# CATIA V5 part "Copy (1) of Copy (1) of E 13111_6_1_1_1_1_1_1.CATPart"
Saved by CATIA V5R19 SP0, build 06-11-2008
Part number: Copy (1) of Copy (1) of E 13111_6_1_1_1_1_1_1
Definition: E 13111_6
Nomenclature: E 13111_6
Source: Unknown
Description: PART-E 13111_6-DESC
Bounding box of the stored display mesh (mm): x -3 to 3, y -3 to 3, z -26 to -8
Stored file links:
  C:\Users\jsmid\Desktop\DP_Smidak_Forma LEGO\Copy (1) of Copy (1) of E 13111_6_1_1_1_1_1_1.CATPart
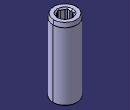
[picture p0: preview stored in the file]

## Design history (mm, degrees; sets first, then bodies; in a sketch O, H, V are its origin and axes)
Body1 "E 13111_6" (main body)
  Solid1: solid without history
